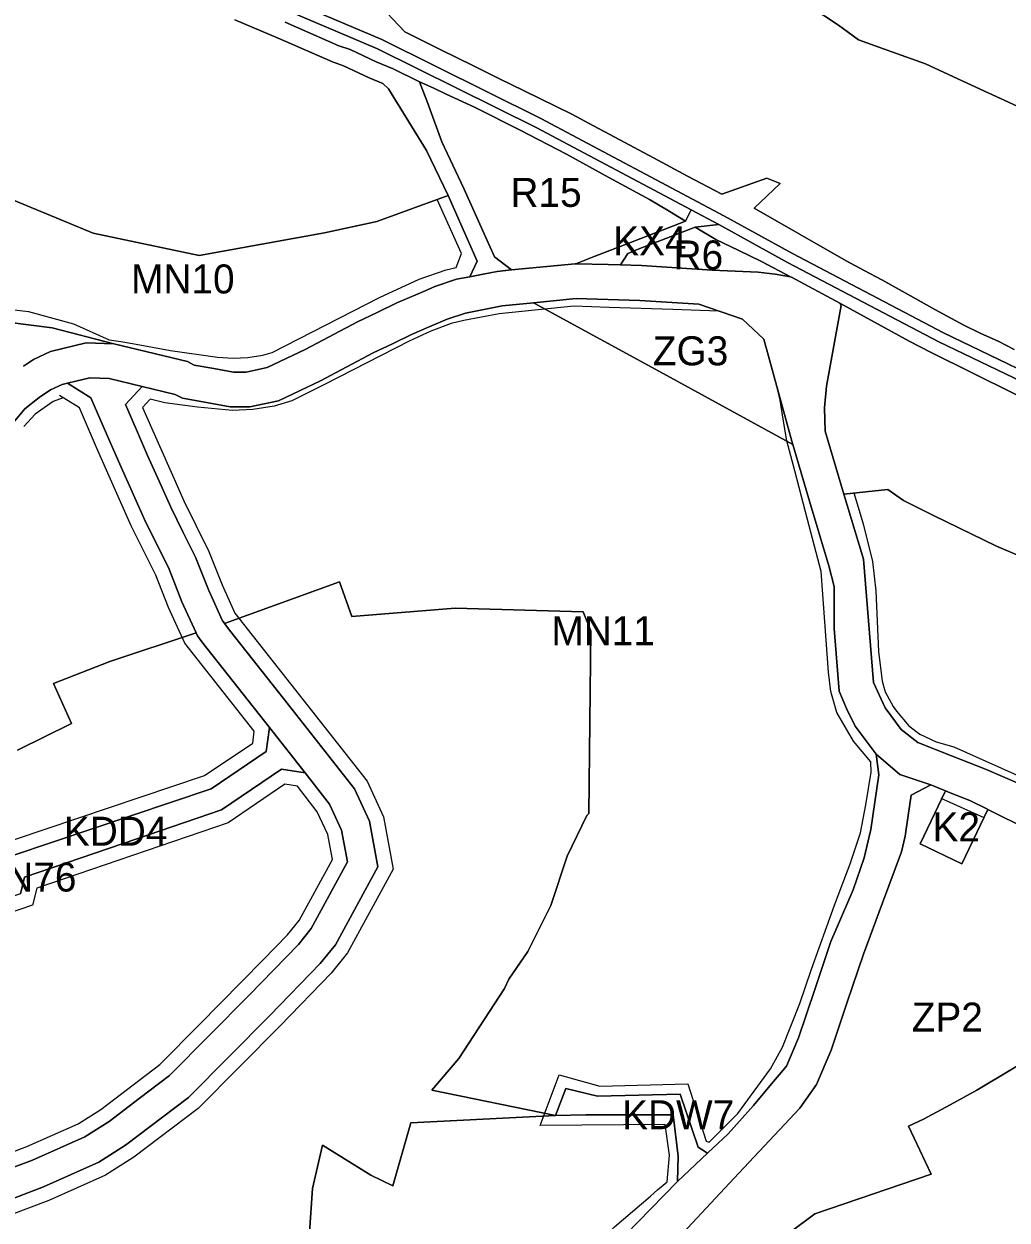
# Model space of a CAD drawing. Extents: x 7428841 to 7433518, y 5545054 to 5546840.
# Drawn here: x 7430323 to 7430661.7, y 5545833.3 to 5546245.5 of the extents above; entities that cross this region are included whole.
import ezdxf

# ---------------------------------------------------------------- set-up
doc = ezdxf.new("R2010")
doc.units = 0
for name, color, linetype in [('linie_rozgraniczajace', 7, 'Continuous'), ('linie_zabudowy_nieprzekraczalne', 7, 'Continuous'), ('oznaczenia_przeznaczen', 7, 'Continuous')]:
    doc.layers.add(name, color=color, linetype=linetype)

msp = doc.modelspace()

# ---------------------------------------------------------------- linework, layer by layer
at = {"layer": 'linie_rozgraniczajace'}
for points in [[(7430395.71, 5546246.95), (7430410.58, 5546240.65), (7430429.34, 5546232.43), (7430433.09, 5546231.11), (7430441.95, 5546227.01), (7430446.69, 5546224.98), (7430448.57, 5546223.18), (7430461.67, 5546201.97), (7430469.14, 5546186.36), (7430444.59, 5546177.43), (7430426.54, 5546173.53), (7430383.37, 5546165.73), (7430346.89, 5546173.43), (7430312.67, 5546187.52), (7430275.76, 5546181.81), (7430248.12, 5546185.73), (7430205.02, 5546191.83), (7430153.69, 5546210.14), (7430145.11, 5546213.38), (7430138.68, 5546217.35), (7430109.51, 5546243.79), (7430073.19, 5546237.15), (7430070.97, 5546244.81), (7430059.92, 5546275.9)], [(7430697.04, 5546111.54), (7430639.75, 5546139.12), (7430587.76, 5546166.42), (7430564.08, 5546179.45), (7430501.06, 5546212.97), (7430446.32, 5546240.13), (7430410.25, 5546255.52)], [(7430410.25, 5546255.52), (7430446.32, 5546240.13), (7430501.06, 5546212.97), (7430564.08, 5546179.45), (7430587.76, 5546166.42), (7430639.75, 5546139.12), (7430697.04, 5546111.54)], [(7430408.91, 5546252.29), (7430444.86, 5546236.95), (7430499.46, 5546209.86), (7430552.89, 5546181.44), (7430550.93, 5546177.57), (7430544.7, 5546181.32), (7430538.46, 5546185.07), (7430531.49, 5546188.83), (7430524.53, 5546192.58), (7430509.95, 5546200.64), (7430493.94, 5546208.96), (7430478.21, 5546216.89), (7430468.43, 5546221.32), (7430464.2, 5546223.45), (7430459.32, 5546225.61), (7430450.19, 5546230.01), (7430444.4, 5546232.49), (7430435.35, 5546236.68), (7430431.54, 5546238.01), (7430412.96, 5546246.16)], [(7430695.58, 5546108.36), (7430638.18, 5546135.99), (7430586.1, 5546163.33), (7430562.41, 5546176.37), (7430552.89, 5546181.44), (7430499.46, 5546209.86), (7430444.86, 5546236.95), (7430408.91, 5546252.29)], [(7430664.15, 5546133.31), (7430658.88, 5546136.13), (7430652.42, 5546138.92), (7430646.84, 5546141.75), (7430636.83, 5546147.06), (7430625.5, 5546153.41), (7430618.59, 5546157.29), (7430612.42, 5546160.6), (7430606.26, 5546163.89), (7430590.43, 5546172.99), (7430574.59, 5546182.08), (7430583.55, 5546190.58), (7430578.92, 5546192.4), (7430563.44, 5546186.82), (7430551.66, 5546193.09), (7430539.89, 5546199.37), (7430533.25, 5546202.95), (7430526.62, 5546206.53), (7430519.18, 5546210.45), (7430511.75, 5546214.38), (7430495.37, 5546222.45), (7430486.62, 5546226.75), (7430477.88, 5546231.05), (7430466.35, 5546236.67), (7430454.25, 5546242.86), (7430444.02, 5546253.57)], [(7430444.02, 5546253.57), (7430454.25, 5546242.86), (7430466.35, 5546236.67), (7430477.88, 5546231.05), (7430486.62, 5546226.75), (7430495.37, 5546222.45), (7430511.75, 5546214.38), (7430519.18, 5546210.45), (7430526.62, 5546206.53), (7430533.25, 5546202.95), (7430539.89, 5546199.37), (7430551.66, 5546193.09), (7430563.44, 5546186.82), (7430578.92, 5546192.4)], [(7430593.83, 5546251.53), (7430603.61, 5546245.07), (7430607.05, 5546242.59), (7430610.49, 5546240.1), (7430616.26, 5546238.02), (7430622.03, 5546235.93), (7430633.57, 5546231.77), (7430649.39, 5546224.48), (7430665.22, 5546217.19)], [(7430610.49, 5546240.1), (7430607.05, 5546242.59), (7430603.61, 5546245.07), (7430593.83, 5546251.53)], [(7430412.96, 5546246.16), (7430431.54, 5546238.01), (7430435.35, 5546236.68), (7430444.4, 5546232.49), (7430450.19, 5546230.01), (7430459.32, 5546225.61), (7430461.98, 5546218.51), (7430466.94, 5546204.85), (7430474.59, 5546188.87), (7430485.1, 5546165.26), (7430490.95, 5546160.73), (7430486.04, 5546160.25), (7430481.18, 5546159.31), (7430476.6, 5546158.41), (7430479.16, 5546163.79), (7430469.14, 5546186.36), (7430461.67, 5546201.97), (7430448.57, 5546223.18), (7430446.69, 5546224.98), (7430441.95, 5546227.01), (7430433.09, 5546231.11), (7430429.34, 5546232.43), (7430410.58, 5546240.65), (7430395.71, 5546246.95)], [(7430665.22, 5546217.19), (7430649.39, 5546224.48), (7430633.57, 5546231.77), (7430622.03, 5546235.93), (7430616.26, 5546238.02), (7430610.49, 5546240.1)], [(7430578.92, 5546192.4), (7430583.55, 5546190.58), (7430574.59, 5546182.08), (7430590.43, 5546172.99), (7430606.26, 5546163.89), (7430612.42, 5546160.6), (7430618.59, 5546157.29), (7430625.5, 5546153.41), (7430636.83, 5546147.06), (7430646.84, 5546141.75), (7430652.42, 5546138.92), (7430658.88, 5546136.13), (7430664.15, 5546133.31)], [(7430312.67, 5546187.52), (7430346.89, 5546173.43), (7430383.37, 5546165.73), (7430426.54, 5546173.53), (7430444.59, 5546177.43), (7430469.14, 5546186.36), (7430479.16, 5546163.79), (7430476.6, 5546158.41), (7430472.03, 5546157.52), (7430464.51, 5546154.98), (7430461.25, 5546153.59), (7430458.01, 5546152.21), (7430451.51, 5546149.44), (7430444.72, 5546146.13), (7430437.93, 5546142.82), (7430419.84, 5546133.27), (7430406.85, 5546127.11), (7430399.52, 5546125.54), (7430395.14, 5546125.51), (7430388.39, 5546126.74), (7430381.65, 5546127.98), (7430379.39, 5546129.17), (7430354.02, 5546135.32), (7430332.77, 5546140.78), (7430310.03, 5546143.69)], [(7430678.14, 5546111.12), (7430635.57, 5546132.28), (7430627.93, 5546136.15), (7430604.07, 5546149.3), (7430587.46, 5546158.21), (7430587.14, 5546158.38), (7430577.07, 5546163.7), (7430569.24, 5546167.49), (7430561.41, 5546171.27), (7430554.3, 5546175.51), (7430562.41, 5546176.37), (7430586.1, 5546163.33), (7430638.18, 5546135.99), (7430695.58, 5546108.36)], [(7430322.81, 5546127.56), (7430326.24, 5546129.84), (7430332.13, 5546132.62), (7430344.46, 5546135.62), (7430354.02, 5546135.32), (7430379.39, 5546129.17), (7430381.65, 5546127.98), (7430388.39, 5546126.74), (7430395.14, 5546125.51), (7430399.52, 5546125.54), (7430406.85, 5546127.11), (7430419.84, 5546133.27), (7430437.93, 5546142.82), (7430444.72, 5546146.13), (7430451.51, 5546149.44), (7430458.01, 5546152.21), (7430461.25, 5546153.59), (7430464.51, 5546154.98), (7430472.03, 5546157.52), (7430476.6, 5546158.41), (7430481.18, 5546159.31), (7430486.04, 5546160.25), (7430490.95, 5546160.73), (7430512.85, 5546162.89), (7430513.08, 5546162.89), (7430524.29, 5546162.57), (7430528.51, 5546162.45), (7430535.74, 5546162.24), (7430560.12, 5546160.68), (7430575.96, 5546160), (7430581.8, 5546159.31), (7430587.14, 5546158.38), (7430587.46, 5546158.21), (7430604.07, 5546149.3), (7430604.59, 5546148.53), (7430602.05, 5546134.63), (7430599.5, 5546120.72), (7430598.83, 5546113.18), (7430598.98, 5546105.23), (7430605.41, 5546083.51), (7430606.63, 5546079.63), (7430612.19, 5546061.04), (7430613.92, 5546039.77), (7430615.65, 5546018.51), (7430619.69, 5546009.78), (7430625.21, 5546002.36), (7430630.92, 5545997.92), (7430642.59, 5545993.27), (7430654.26, 5545988.63), (7430677.65, 5545978.55)], [(7430683.11, 5545960.86), (7430655.11, 5545974.8), (7430655, 5545974.86), (7430648.91, 5545977.89), (7430642.15, 5545980.57), (7430640.46, 5545981.24), (7430635.4, 5545983.25), (7430624.71, 5545986.79), (7430616.56, 5545993.9), (7430609.42, 5546003.49), (7430606.39, 5546009.62), (7430603.85, 5546015.61), (7430602.09, 5546037.21), (7430602.12, 5546051.62), (7430600.34, 5546058.81), (7430593.68, 5546081.08), (7430587.85, 5546100.57), (7430587.51, 5546101.7), (7430577.91, 5546136.89), (7430570.54, 5546143.75), (7430555.47, 5546148.96), (7430535.18, 5546150.25), (7430513.27, 5546150.88), (7430498.55, 5546149.43), (7430487.78, 5546148.37), (7430475.12, 5546145.89), (7430468.79, 5546143.76), (7430462.64, 5546141.14), (7430456.5, 5546138.52), (7430449.93, 5546135.32), (7430443.36, 5546132.12), (7430434.29, 5546127.33), (7430425.21, 5546122.54), (7430410.74, 5546115.68), (7430400.82, 5546113.54), (7430394.09, 5546113.51), (7430385.88, 5546115.01), (7430377.66, 5546116.5), (7430375.1, 5546117.86), (7430363.75, 5546120.61), (7430352.39, 5546123.36), (7430345.71, 5546123.58), (7430340.93, 5546122.41), (7430337.99, 5546121.7), (7430336.15, 5546121.25), (7430332.16, 5546119.37), (7430328.23, 5546116.75), (7430323.33, 5546112.89), (7430319.89, 5546108.68)], [(7430716.89, 5546040.51), (7430658.06, 5546065.53), (7430636.31, 5546076.15), (7430625.97, 5546081.23), (7430620.61, 5546085.06), (7430605.41, 5546083.51), (7430598.98, 5546105.23), (7430598.83, 5546113.18), (7430599.5, 5546120.72), (7430602.05, 5546134.63), (7430604.59, 5546148.53), (7430604.07, 5546149.3), (7430627.93, 5546136.15), (7430635.57, 5546132.28), (7430678.14, 5546111.12)], [(7430310.03, 5546143.69), (7430332.77, 5546140.78), (7430354.02, 5546135.32), (7430344.46, 5546135.62), (7430332.13, 5546132.62), (7430326.24, 5546129.84), (7430322.81, 5546127.56)], [(7430312.65, 5545848.93), (7430325.91, 5545853.94), (7430344.01, 5545862), (7430352.31, 5545867.28), (7430362.72, 5545875.17), (7430373.14, 5545883.06), (7430386.83, 5545896.89), (7430400.52, 5545910.72), (7430417.58, 5545928.28), (7430421.99, 5545933.73), (7430434.49, 5545956.73), (7430432.45, 5545967.68), (7430428.32, 5545976.6), (7430419.93, 5545987.45), (7430407.64, 5546003.07), (7430384.29, 5546032.62), (7430382.75, 5546034.63), (7430382.31, 5546035.67), (7430377.45, 5546046.37), (7430373.03, 5546057.62), (7430364.51, 5546074.73), (7430356.44, 5546092.77), (7430352.61, 5546101.59), (7430346.1, 5546116.62), (7430337.99, 5546121.7), (7430340.93, 5546122.41), (7430345.71, 5546123.58), (7430352.39, 5546123.36), (7430363.75, 5546120.61), (7430357.96, 5546114.38), (7430361.77, 5546105.59), (7430365.59, 5546096.8), (7430369.58, 5546087.89), (7430373.57, 5546078.98), (7430377.74, 5546070.5), (7430382.16, 5546061.71), (7430386.67, 5546050.26), (7430391.37, 5546039.85), (7430392.05, 5546038.95), (7430392.07, 5546038.93), (7430394.25, 5546036.06), (7430414.13, 5546010.85), (7430436.9, 5545981.86)], [(7430319.89, 5546108.68), (7430323.33, 5546112.89), (7430328.23, 5546116.75), (7430332.16, 5546119.37), (7430336.15, 5546121.25), (7430337.99, 5546121.7), (7430346.1, 5546116.62), (7430352.61, 5546101.59), (7430356.44, 5546092.77), (7430364.51, 5546074.73), (7430373.03, 5546057.62), (7430377.45, 5546046.37), (7430382.31, 5546035.67), (7430352.55, 5546025.78), (7430333.18, 5546018.26), (7430339.37, 5546004.41), (7430320.75, 5545995.28)], [(7430677.65, 5545978.55), (7430654.26, 5545988.63), (7430642.59, 5545993.27), (7430630.92, 5545997.92), (7430625.21, 5546002.36), (7430619.69, 5546009.78), (7430615.65, 5546018.51), (7430613.92, 5546039.77), (7430612.19, 5546061.04), (7430606.63, 5546079.63), (7430605.41, 5546083.51), (7430620.61, 5546085.06), (7430625.97, 5546081.23), (7430636.31, 5546076.15), (7430658.06, 5546065.53), (7430716.89, 5546040.51)], [(7430315.92, 5545839.47), (7430329.71, 5545844.69), (7430348.76, 5545853.17), (7430358.02, 5545859.07), (7430379.74, 5545875.52), (7430407.66, 5545903.72), (7430425.08, 5545921.64), (7430430.34, 5545928.16), (7430444.96, 5545955.06), (7430442.05, 5545970.74), (7430436.9, 5545981.86), (7430414.13, 5546010.85), (7430394.25, 5546036.06), (7430392.07, 5546038.93), (7430431.74, 5546053.2), (7430435.91, 5546041.26), (7430471.61, 5546044.17), (7430515.64, 5546042.92), (7430518.3, 5546036.41), (7430517.59, 5545973.42), (7430516.89, 5545972.65), (7430510.13, 5545958.72), (7430504.56, 5545941.71), (7430496.6, 5545925.86), (7430490, 5545916.26), (7430488.53, 5545913.11), (7430472.83, 5545888.92), (7430463.51, 5545878.02), (7430506.1, 5545869.32), (7430456.34, 5545866.79), (7430450.14, 5545845.05), (7430442.53, 5545848.78), (7430425.88, 5545859.06), (7430422.45, 5545844.1), (7430420.71, 5545819.01)], [(7430320.75, 5545995.28), (7430339.37, 5546004.41), (7430333.18, 5546018.26), (7430352.55, 5546025.78), (7430382.31, 5546035.67), (7430382.75, 5546034.63), (7430384.29, 5546032.62), (7430407.64, 5546003.07), (7430406.5, 5545994.8), (7430387.48, 5545981.93), (7430319.19, 5545958.9)], [(7430530.39, 5545828.27), (7430538.96, 5545837.09), (7430548.14, 5545846.52), (7430558.45, 5545856.35), (7430565.61, 5545862.98), (7430574.32, 5545872.74), (7430580.02, 5545879.51), (7430585.71, 5545886.27), (7430589.9, 5545896.13), (7430595.43, 5545912.68), (7430600.97, 5545929.24), (7430608.66, 5545947.14), (7430612.51, 5545958.14), (7430614.76, 5545967.86), (7430617.56, 5545986.69), (7430616.56, 5545993.9), (7430624.71, 5545986.79), (7430635.4, 5545983.25), (7430628.71, 5545979.66), (7430627.63, 5545972.65), (7430626.56, 5545965.64), (7430625.31, 5545960.22), (7430618.75, 5545942.59), (7430612.19, 5545924.96), (7430606.66, 5545908.42), (7430601.13, 5545891.88), (7430596.07, 5545879.97), (7430590.3, 5545871.87), (7430569.32, 5545849.46), (7430548.34, 5545827.05)], [(7430321.76, 5545945.71), (7430323.22, 5545951.5), (7430357.15, 5545963.1), (7430391.08, 5545974.71), (7430411.76, 5545988.73), (7430419.93, 5545987.45), (7430428.32, 5545976.6), (7430432.45, 5545967.68), (7430434.49, 5545956.73), (7430421.99, 5545933.73), (7430417.58, 5545928.28), (7430400.52, 5545910.72), (7430386.83, 5545896.89), (7430373.14, 5545883.06), (7430362.72, 5545875.17), (7430352.31, 5545867.28), (7430344.01, 5545862), (7430325.91, 5545853.94), (7430312.65, 5545848.93)], [(7430548.34, 5545827.05), (7430569.32, 5545849.46), (7430590.3, 5545871.87), (7430596.07, 5545879.97), (7430601.13, 5545891.88), (7430606.66, 5545908.42), (7430612.19, 5545924.96), (7430618.75, 5545942.59), (7430625.31, 5545960.22), (7430626.56, 5545965.64), (7430627.63, 5545972.65), (7430628.71, 5545979.66), (7430635.4, 5545983.25), (7430640.46, 5545981.24), (7430631.71, 5545962.91), (7430646.14, 5545956.01), (7430655.11, 5545974.8), (7430683.11, 5545960.86)], [(7430436.9, 5545981.86), (7430442.05, 5545970.74), (7430444.96, 5545955.06), (7430430.34, 5545928.16), (7430425.08, 5545921.64), (7430407.66, 5545903.72), (7430379.74, 5545875.52), (7430358.02, 5545859.07), (7430348.76, 5545853.17), (7430329.71, 5545844.69), (7430315.92, 5545839.47)], [(7430663.1, 5545603.69), (7430635.16, 5545655.99), (7430586.55, 5545745.89), (7430555.14, 5545805.32), (7430595.45, 5545835.45), (7430635.56, 5545849.06), (7430627.71, 5545865.6), (7430632.95, 5545868.01), (7430642.11, 5545873.01), (7430651.28, 5545878), (7430675.25, 5545892.35)], [(7430675.25, 5545892.35), (7430651.28, 5545878), (7430642.11, 5545873.01), (7430632.95, 5545868.01), (7430627.71, 5545865.6), (7430635.56, 5545849.06), (7430595.45, 5545835.45), (7430555.14, 5545805.32)], [(7430420.71, 5545819.01), (7430422.45, 5545844.1), (7430425.88, 5545859.06), (7430442.53, 5545848.78), (7430450.14, 5545845.05), (7430456.34, 5545866.79), (7430506.1, 5545869.32), (7430516.56, 5545869.49), (7430546.63, 5545869.56), (7430548.39, 5545855.3), (7430548.14, 5545846.63), (7430548.14, 5545846.52), (7430538.96, 5545837.09), (7430530.39, 5545828.27)]]:
    msp.add_lwpolyline(points, dxfattribs=at)
for points in [[(7430459.32, 5546225.61), (7430464.2, 5546223.45), (7430468.43, 5546221.32), (7430478.21, 5546216.89), (7430493.94, 5546208.96), (7430509.95, 5546200.64), (7430524.53, 5546192.58), (7430531.49, 5546188.83), (7430538.46, 5546185.07), (7430544.7, 5546181.32), (7430550.93, 5546177.57), (7430531.42, 5546169.93), (7430519.43, 5546165.32), (7430513.08, 5546162.89), (7430512.85, 5546162.89), (7430490.95, 5546160.73), (7430485.1, 5546165.26), (7430474.59, 5546188.87), (7430466.94, 5546204.85), (7430461.98, 5546218.51)], [(7430513.08, 5546162.89), (7430519.43, 5546165.32), (7430531.42, 5546169.93), (7430550.93, 5546177.57), (7430552.89, 5546181.44), (7430562.41, 5546176.37), (7430554.3, 5546175.51), (7430547.13, 5546172.73), (7430535.2, 5546168.11), (7430531.01, 5546166.37), (7430528.51, 5546162.45), (7430524.29, 5546162.57)], [(7430528.51, 5546162.45), (7430531.01, 5546166.37), (7430535.2, 5546168.11), (7430547.13, 5546172.73), (7430554.3, 5546175.51), (7430561.41, 5546171.27), (7430569.24, 5546167.49), (7430577.07, 5546163.7), (7430587.14, 5546158.38), (7430581.8, 5546159.31), (7430575.96, 5546160), (7430560.12, 5546160.68), (7430535.74, 5546162.24)], [(7430357.96, 5546114.38), (7430363.75, 5546120.61), (7430375.1, 5546117.86), (7430377.66, 5546116.5), (7430385.88, 5546115.01), (7430394.09, 5546113.51), (7430400.82, 5546113.54), (7430410.74, 5546115.68), (7430425.21, 5546122.54), (7430434.29, 5546127.33), (7430443.36, 5546132.12), (7430449.93, 5546135.32), (7430456.5, 5546138.52), (7430462.64, 5546141.14), (7430468.79, 5546143.76), (7430475.12, 5546145.89), (7430487.78, 5546148.37), (7430498.55, 5546149.43), (7430543.2, 5546125), (7430587.85, 5546100.57), (7430593.68, 5546081.08), (7430600.34, 5546058.81), (7430602.12, 5546051.62), (7430602.09, 5546037.21), (7430603.85, 5546015.61), (7430606.39, 5546009.62), (7430609.42, 5546003.49), (7430616.56, 5545993.9), (7430617.56, 5545986.69), (7430614.76, 5545967.86), (7430612.51, 5545958.14), (7430608.66, 5545947.14), (7430600.97, 5545929.24), (7430595.43, 5545912.68), (7430589.9, 5545896.13), (7430585.71, 5545886.27), (7430580.02, 5545879.51), (7430574.32, 5545872.74), (7430565.61, 5545862.98), (7430558.45, 5545856.35), (7430555.27, 5545858.34), (7430549.05, 5545876.61), (7430520.56, 5545875.94), (7430509.64, 5545878.65), (7430506.1, 5545869.32), (7430463.51, 5545878.02), (7430472.83, 5545888.92), (7430488.53, 5545913.11), (7430490, 5545916.26), (7430496.6, 5545925.86), (7430504.56, 5545941.71), (7430510.13, 5545958.72), (7430516.89, 5545972.65), (7430517.59, 5545973.42), (7430518.3, 5546036.41), (7430515.64, 5546042.92), (7430471.61, 5546044.17), (7430435.91, 5546041.26), (7430431.74, 5546053.2), (7430392.07, 5546038.93), (7430392.05, 5546038.95), (7430391.37, 5546039.85), (7430386.67, 5546050.26), (7430382.16, 5546061.71), (7430377.74, 5546070.5), (7430373.57, 5546078.98), (7430369.58, 5546087.89), (7430365.59, 5546096.8), (7430361.77, 5546105.59)], [(7430498.55, 5546149.43), (7430513.27, 5546150.88), (7430535.18, 5546150.25), (7430555.47, 5546148.96), (7430570.54, 5546143.75), (7430577.91, 5546136.89), (7430587.51, 5546101.7), (7430587.85, 5546100.57), (7430543.2, 5546125)], [(7430298.13, 5545956.66), (7430313.9, 5545962.12), (7430319.19, 5545958.9), (7430387.48, 5545981.93), (7430406.5, 5545994.8), (7430407.64, 5546003.07), (7430419.93, 5545987.45), (7430411.76, 5545988.73), (7430391.08, 5545974.71), (7430357.15, 5545963.1), (7430323.22, 5545951.5), (7430321.76, 5545945.71), (7430307.29, 5545940.77), (7430302.71, 5545948.72)], [(7430631.71, 5545962.91), (7430640.46, 5545981.24), (7430642.15, 5545980.57), (7430648.91, 5545977.89), (7430655, 5545974.86), (7430655.11, 5545974.8), (7430646.14, 5545956.01)], [(7430506.1, 5545869.32), (7430509.64, 5545878.65), (7430520.56, 5545875.94), (7430549.05, 5545876.61), (7430555.27, 5545858.34), (7430558.45, 5545856.35), (7430548.14, 5545846.52), (7430548.14, 5545846.63), (7430548.39, 5545855.3), (7430546.63, 5545869.56), (7430516.56, 5545869.49)]]:
    msp.add_lwpolyline(points, close=True, dxfattribs=at)
at = {"layer": 'linie_zabudowy_nieprzekraczalne'}
for points in [[(7430473.76, 5546166.38), (7430465.36, 5546184.98)], [(7430471.9, 5546161.55), (7430473.76, 5546166.38)], [(7430459.2, 5546157.52), (7430468.51, 5546160.74), (7430471.9, 5546161.55)], [(7430352.42, 5546136.67), (7430356.4, 5546136.07), (7430359.75, 5546135.54), (7430364.2, 5546134.75), (7430373.48, 5546132.96), (7430389.69, 5546130.72), (7430395.05, 5546130.36), (7430400.1, 5546130.61), (7430405.3, 5546131.37), (7430408.53, 5546132.34), (7430445.44, 5546151.22), (7430459.2, 5546157.52)], [(7430289.42, 5546150.77), (7430307.96, 5546148.42), (7430324.57, 5546146.39), (7430340.12, 5546142.19), (7430352.42, 5546136.67)], [(7430614.79, 5545991.17), (7430614.79, 5545991.17), (7430608.79, 5545998.34), (7430603.05, 5546008.17), (7430600.93, 5546015.47), (7430600.15, 5546022.09), (7430597.65, 5546056.84), (7430595.98, 5546063.39), (7430592.27, 5546077.38), (7430588.58, 5546091.45), (7430585.79, 5546101.79), (7430584.57, 5546109.28), (7430583.55, 5546115.88), (7430582.71, 5546119.3), (7430582.71, 5546119.3), (7430577.91, 5546136.89), (7430577.91, 5546136.89), (7430570.54, 5546143.75), (7430562.32, 5546146.56), (7430546.5, 5546147.13), (7430524.58, 5546147.84), (7430512.47, 5546148.23), (7430486.69, 5546145.56), (7430474.52, 5546143.34), (7430470.2, 5546142.23), (7430463.22, 5546139.69), (7430455.68, 5546136.24), (7430426.52, 5546121.25), (7430415.28, 5546115.58), (7430409.22, 5546113.75), (7430401.85, 5546112.67), (7430394.89, 5546112.33), (7430382.85, 5546113.4), (7430371.59, 5546114.9), (7430366.45, 5546116.18)], [(7430366.4, 5546116.12), (7430363.84, 5546113.37), (7430374.13, 5546089.96), (7430378.09, 5546081.11), (7430382.22, 5546072.73), (7430386.73, 5546063.75), (7430391.27, 5546052.21), (7430395.69, 5546042.42), (7430441.19, 5545984.49), (7430446.85, 5545972.27), (7430450.2, 5545954.23), (7430434.51, 5545925.37), (7430428.82, 5545918.32), (7430411.23, 5545900.22), (7430383.04, 5545871.75), (7430360.88, 5545854.96), (7430351.13, 5545848.75), (7430331.61, 5545840.06), (7430303.48, 5545829.43), (7430291.26, 5545827.1), (7430272.4, 5545825.1), (7430246.47, 5545824.6), (7430227.18, 5545824.13)], [(7430336.56, 5546116.71), (7430333.07, 5546115.4), (7430326.83, 5546111.07), (7430322.98, 5546106.74)], [(7430402.33, 5546001.78), (7430378.41, 5546032.09), (7430372.85, 5546044.42), (7430368.45, 5546055.59), (7430364.22, 5546064.09), (7430359.99, 5546072.6), (7430351.87, 5546090.75), (7430348.03, 5546099.59), (7430342.13, 5546113.2), (7430335.24, 5546117.52)], [(7430608.94, 5546083.87), (7430612.09, 5546073.25), (7430615.39, 5546060.23), (7430616.46, 5546050.13), (7430617.44, 5546029.27), (7430618.63, 5546019.05), (7430619.71, 5546015.32), (7430622.51, 5546010.32), (7430623.57, 5546008.72), (7430627.85, 5546003.61), (7430631.69, 5546000.75), (7430637.27, 5545998.13), (7430643.32, 5545996.34), (7430671.86, 5545983.62), (7430698.68, 5545969.71)], [(7430417.21, 5545982.8), (7430412.93, 5545983.48), (7430393.33, 5545970.19), (7430327.41, 5545947.65), (7430325.95, 5545941.85), (7430305.02, 5545934.71), (7430290.77, 5545959.4), (7430314.49, 5545967.61), (7430319.8, 5545964.38), (7430385.24, 5545986.45), (7430401.85, 5545997.69), (7430402.33, 5546001.78)], [(7430559.02, 5545860.07), (7430568.9, 5545869.98), (7430580.22, 5545885.43), (7430584.3, 5545892.82), (7430590.3, 5545907.95), (7430594.35, 5545919.71), (7430602.27, 5545941.79), (7430607.66, 5545956.08), (7430611.23, 5545966.73), (7430613, 5545976.38), (7430614.9, 5545987.69), (7430614.79, 5545991.17)], [(7430303.75, 5545850.89), (7430324, 5545858.57), (7430341.64, 5545866.42), (7430349.45, 5545871.39), (7430369.83, 5545886.83), (7430383.39, 5545900.53), (7430405.39, 5545922.91), (7430413.84, 5545931.6), (7430417.81, 5545936.52), (7430429.25, 5545957.56), (7430427.65, 5545966.15), (7430424.02, 5545973.98), (7430417.21, 5545982.8)], [(7430653.82, 5545971.91), (7430641.1, 5545977.67), (7430639.04, 5545978.59)], [(7430544.56, 5545846.49), (7430545.36, 5545855.63), (7430543.93, 5545866.25), (7430500.89, 5545865.89), (7430507.4, 5545883.29), (7430521.41, 5545879.37), (7430551.73, 5545880.25), (7430557.99, 5545860.46), (7430559.02, 5545860.07)], [(7430322.99, 5545732.04), (7430338.17, 5545740.16), (7430349.85, 5545743.75), (7430361.53, 5545747.33), (7430371.52, 5545750.51), (7430383.04, 5545754.49), (7430396.69, 5545759.12), (7430408.25, 5545763.16), (7430425.96, 5545767.9), (7430443.67, 5545772.63), (7430463.9, 5545781.4), (7430471.51, 5545785.28), (7430479.11, 5545789.16), (7430489.75, 5545795.47), (7430493.25, 5545798.12), (7430494.48, 5545799.04), (7430496.78, 5545800.75), (7430506.43, 5545810.85), (7430515.94, 5545820.7), (7430526.43, 5545830.89), (7430538.8, 5545841.5), (7430541.3, 5545843.63), (7430544.56, 5545846.49)]]:
    msp.add_lwpolyline(points, dxfattribs=at)

# ---------------------------------------------------------------- texts
at = {"layer": 'oznaczenia_przeznaczen'}
for s, p in [('R15', (7430490.6, 5546182.48)), ('KX4', (7430526.02, 5546165.77)), ('R6', (7430546.81, 5546160.9)), ('MN10', (7430359.91, 5546152.64)), ('ZG3', (7430539.65, 5546127.86)), ('MN11', (7430504.7, 5546031.41)), ('KDD4', (7430336.76, 5545962.29)), ('K2', (7430636.02, 5545963.8)), ('MN76', (7430305.41, 5545946.5)), ('ZP2', (7430628.83, 5545898.22)), ('KDW7', (7430529.07, 5545864.56))]:
    msp.add_text(s, height=10, dxfattribs=at).set_placement(p)

doc.saveas('drawing.dxf')
